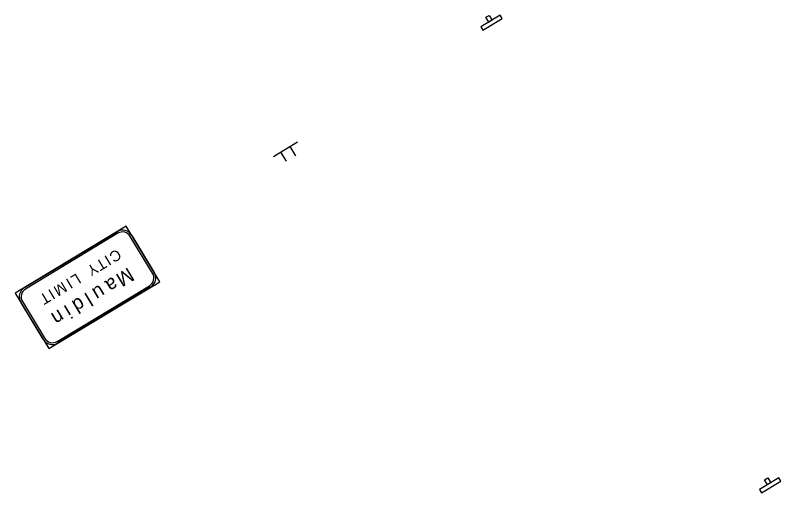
# Model space of a CAD drawing. Extents: x 1581789 to 1622364, y 1043167 to 1103486.
# Drawn here: x 1613644.8 to 1613928.4, y 1085534.4 to 1085711.2 of the extents above; entities that cross this region are included whole.
import ezdxf

# ---------------------------------------------------------------- set-up
doc = ezdxf.new("R2010")
doc.units = 0
doc.layers.add('RD_PD_ALT1_TrvlWay', color=7, linetype='Continuous')
doc.layers.add('RD_PD_ALT1_TX', color=7, linetype='Continuous')

msp = doc.modelspace()

# ---------------------------------------------------------------- linework, layer by layer
at = {"layer": 'RD_PD_ALT1_TrvlWay'}
for p, q in [((1613740.44, 1085658.9), (1613749.38, 1085664.29)), ((1613746.56, 1085662.59), (1613748.62, 1085659.17)), ((1613743.12, 1085660.52), (1613745.18, 1085657.1))]:
    msp.add_line(p, q, dxfattribs=at)
for points in [[(1613685.96, 1085633.07), (1613644.84, 1085608.29), (1613657.23, 1085587.74), (1613698.34, 1085612.51), (1613685.96, 1085633.07), (1613685.96, 1085633.07)], [(1613648.27, 1085610.36), (1613682.53, 1085631)], [(1613682.87, 1085630.43), (1613648.61, 1085609.79)], [(1613695.71, 1085615.6), (1613687.45, 1085629.3)], [(1613688.02, 1085629.64), (1613696.28, 1085615.94)], [(1613660.31, 1085590.37), (1613694.57, 1085611.02)], [(1613694.92, 1085610.45), (1613660.66, 1085589.8)], [(1613655.17, 1085591.16), (1613646.91, 1085604.87)], [(1613647.48, 1085605.21), (1613655.74, 1085591.51)]]:
    msp.add_lwpolyline(points, dxfattribs=at)
for centre, radius, start, end in [((1613684.59, 1085627.58), 4, 31.0766, 121.0769), ((1613684.59, 1085627.58), 3.33, 31.0766, 121.0769), ((1613692.85, 1085613.88), 4, 301.077, 31.0766), ((1613692.85, 1085613.88), 3.33, 301.077, 31.0766), ((1613650.33, 1085606.93), 4, 121.0769, 211.0771), ((1613650.33, 1085606.93), 3.33, 121.0769, 211.0771), ((1613658.59, 1085593.23), 4, 211.0768, 301.077), ((1613658.59, 1085593.23), 3.33, 211.0768, 301.077)]:
    msp.add_arc(centre, radius, start, end, dxfattribs=at)
at = {"layer": 'RD_PD_ALT1_TX'}
for points in [[(1613818.02, 1085705.66), (1613825.16, 1085709.96), (1613824.45, 1085711.15), (1613817.31, 1085706.85)], [(1613819.21, 1085710.43), (1613820.4, 1085711.14), (1613821.47, 1085709.36), (1613820.28, 1085708.64)], [(1613921.26, 1085534.37), (1613928.4, 1085538.67), (1613927.68, 1085539.86), (1613920.55, 1085535.56)], [(1613922.44, 1085539.13), (1613923.63, 1085539.85), (1613924.71, 1085538.06), (1613923.52, 1085537.35)]]:
    msp.add_lwpolyline(points, close=True, dxfattribs=at)

# ---------------------------------------------------------------- texts
at = {"layer": 'RD_PD_ALT1_TrvlWay'}
for s, height, p in [('I', 4, (1613678.74, 1085622.49)), ('C', 4, (1613682.57, 1085624.8)), ('Y', 4, (1613673.98, 1085619.62)), ('T', 4, (1613677.04, 1085621.47)), ('M', 5.33, (1613686.72, 1085617.96)), ('I', 4, (1613664.48, 1085613.9)), ('L', 4, (1613667.55, 1085615.75)), ('a', 5.33, (1613681.02, 1085614.53)), ('M', 4, (1613662.42, 1085612.66)), ('u', 5.33, (1613676.19, 1085611.62)), ('T', 4, (1613656.23, 1085608.93)), ('I', 4, (1613657.93, 1085609.95)), ('l', 5.33, (1613671.34, 1085608.69)), ('d', 5.33, (1613668.71, 1085607.11)), ('n', 5.33, (1613661.04, 1085602.49)), ('i', 5.33, (1613663.75, 1085604.12))]:
    msp.add_text(s, height=height, rotation=211.0768, dxfattribs=at).set_placement(p)

doc.saveas('drawing.dxf')
